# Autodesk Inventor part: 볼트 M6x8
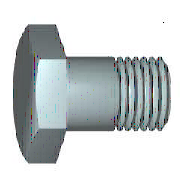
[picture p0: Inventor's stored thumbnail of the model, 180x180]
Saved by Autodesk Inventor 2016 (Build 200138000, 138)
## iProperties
Created: 2012-02
Part Number: 볼트 M6x8
Material: 강철, 연강
Description: 6각 머리 볼트 및 6각 머리 나사
Document SubType Name: Modeling
Standard: KS B 1002
Designer: mduedu
Standards Organization: KS
Language: ko-KR
Size Designation: C  M 6 x 12
Categories: <MemberInstance><Categories><Category DisplayName="조임쇠" InternalName="e4da775c-781d-43d5-af7c-5136215cf5a6" Mnemonic="FSTN"><Category DisplayName="볼트" InternalN
Density: 1 g/cm^3
Appearance: 강철
IsCustomPart: 1
Author: mduedu
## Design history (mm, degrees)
sketch "스케치1"
  geometry: L1 (0, 3)-(8, 3); L2 (8, 3)-(8, 0); L3 (8, 0)-(0, 0); L4 (-2.4, 0)-(14.4, 0) reference; L5 (0, -0.6)-(0, 3.6) reference; L6 (0, 3)-(0, 0)
  constraints: 8 end point, 3 point on line, 1 collinear
  dimensions: "d2" = 6 diameter of L1 L3 (= GD); "d59" = 8 distance between parallel lines of L2 L5 (= NLG)
revolve "본체" sketch "스케치1" stored, may be unused: angle "d12" = 90 deg
sketch "스케치2"
  geometry: L1 (0, 5.774)-(5, 2.887); L2 (5, 2.887)-(5, -2.887); L3 (5, -2.887)-(0, -5.774); L4 (0, -5.774)-(-5, -2.887); L5 (-5, -2.887)-(-5, 2.887); L6 (-5, 2.887)-(0, 5.774); L7 (-7, 0)-(7, 0) reference; L8 (0, 8.083)-(0, -8.083) reference; 2 further points
  constraints: 12 end point, 2 midpoint, 1 coincident, 1 vertical, 11 other
  dimensions: "d11" = 10 distance between parallel lines of L5 L2 (= SW)
extrude "머리" join sketch "스케치2" distance "d3" = 4 (= KOH); taper "d4" = 0 deg
revolve "모따기1" stored, may be unused: angle "d21" = 90 deg
workplane "Work Plane1"
body "Solid1"
feature "스레드" dims "d15" = 9 (= GEL), "d16" = 0
chamfer "모따기2" distance "d6" = 0.61345 (= -0.5 x SPD + 0.5 x GD); stored, may be unused: second distance "d7" = 0.61355 (computed from GUL), angle "d55" = 45 deg
sketch "스케치4"
  geometry: L1 (-3.423, 6)-(-4, 5); L2 (-1.1, 0)-(-0.234, 0); L3 (-4.753, 0)-(0.519, 0) reference; L4 (-4, 6)-(-3.423, 6); L5 (-4, 5)-(-4, 6); L6 (0, 7.2)-(0, -1.2) reference
  constraints: 8 end point, 1 parallel, 1 perpendicular, 1 point on line
  dimensions: "d65" = 10 diameter of L1.end L2 (= SW); "d67" = 30 deg angle of L1 L5 (= ANG1); "d68" = 12 diameter of L4 L2 (= 1.2 x SW); "d69" = 4 distance between parallel lines of L5 L6 (= KOH)
other parameters: "NLG" = 8 [user parameter; used in 1 equation term], "GD" = 6 (= NND) [user parameter; used in 2 equation terms], "BDM" = 6 (= NND) [user parameter], "KOH" = 4 [user parameter; used in 2 equation terms], "GEL" = 9 [user parameter; used in 1 equation term], "SW" = 10 [user parameter; used in 5 equation terms], "SPD" = 4.7731 (= NND - 1.2269 x PTC) [user parameter; used in 1 equation term], "SD2" = 6 (= NND) [user parameter], "SD" = 0 [user parameter], "ANG1" = 30 deg [user parameter; used in 1 equation term], "GAL" = 0.61345 (= 0.61345 x PTC) [user parameter], "GUL" = 0.61345 (= 0.61345 x PTC) [user parameter; used in 1 equation term], "d8" = 0, "RR" = 0.25 [user parameter], "d58" = 0, "RR1" = 0.1 [user parameter], "GD1" = 4.7731 (= THREADDIA - 1.2269 x PTC) [user parameter], "THREADDIA" = 6 [user parameter; used in 1 equation term], "TOA" = 30 deg [user parameter], "PTC" = 1 [user parameter; used in 5 equation terms], "NND" = 6 [user parameter; used in 4 equation terms], "E0" = 11.55 (= 1.155 x SW) [user parameter]
